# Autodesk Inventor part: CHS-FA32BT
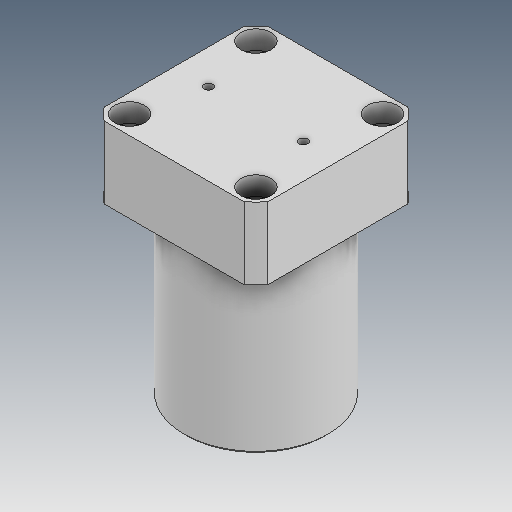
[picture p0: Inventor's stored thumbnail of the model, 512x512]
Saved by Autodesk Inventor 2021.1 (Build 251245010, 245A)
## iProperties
Created: 2019-04
Part Number: CHS-FA32BT
Material: Ogólny
Document SubType Name: Modeling
Designer: user
Density: 1 g/cm^3
Appearance: Domyślna
Author: user
Revision Number: ÈÎºÎ
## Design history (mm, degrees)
feature "ÊäÈë1"
node "Bryła1"
